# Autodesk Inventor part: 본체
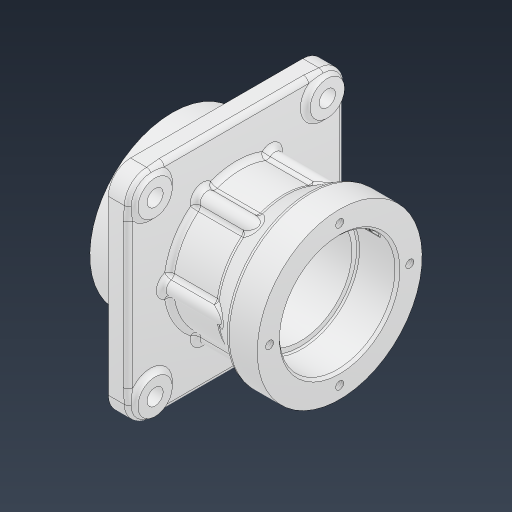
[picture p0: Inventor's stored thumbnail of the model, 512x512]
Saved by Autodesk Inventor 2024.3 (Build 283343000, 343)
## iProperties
Created: 2025-08
Part Number: 본체
Material: 알루미늄 6061
Document SubType Name: Modeling
Designer: user
Density: 2.7 g/cm^3
Appearance: 알루미늄 - 평지
Mass: 392.632 g
Surface Area: 389.994 cm^2
Volume: 145.419 cm^3
Author: user
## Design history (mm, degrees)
sketch "스케치1"
  geometry: L1 (34, 33.5)-(34, 0); L2 (34, 0)-(-34, 0); L3 (-34, 0)-(-34, 33.5); L4 (-34, 33.5)-(34, 0); L5 (34, 33.5)-(-34, 0); L6 (-21, 38.5)-(-16, 38.5); L7 (-16, 38.5)-(-16, 0); L8 (-16, 0)-(-21, 0); L9 (-21, 0)-(-21, 38.5); L10 (-21, 38.5)-(-16, 0); L11 (-16, 38.5)-(-21, 0); L12 (22, 33.5)-(22, 0); L13 (12, 27.5)-(12, 0); L14 (21.821, 27.5)-(12, 27.5); L15 (-34, 33.5)-(-20.351, 33.5); L16 (22, 33.5)-(34, 33.5); L17 (22, 33.5)-(12, 27.5); L18 (12, 27.5)-(-16, 27.5); L19 (-20.351, 33.5)-(-16, 33.5); 10 further points
  constraints: 38 end point, 8 midpoint, 7 perpendicular, 7 point on line, 6 parallel, 4 horizontal, 1 coincident, 1 vertical
  dimensions: "d0" = 68 distance of L1.end L2.end; "d3" = 5 distance of L7.end L8.end; "d5" = 13 distance from line of point (-34, 16.75) L9; "d6" = 77 diameter of L6 L2; "d14" = 12 distance from line of point (34, 16.75) L12; "d16" = 22 distance between parallel lines of L1 L13; "d17" = 55 diameter of L14 L2; "d18" = 67 diameter of L16 L2
revolve "회전1" sketch "스케치1" stored, may be unused: angle "d7" = 360 deg
sketch "스케치4"
  geometry: L1 (44, -44)-(-44, -44); L2 (-44, -44)-(-44, 44); L3 (-44, 44)-(44, 44); L4 (44, 44)-(44, -44); L5 (44, -44)-(-44, 44); L6 (-44, -44)-(44, 44); C1 r 27.5 at (0, 0) reference
  constraints: 12 end point, 2 midpoint, 2 parallel, 1 horizontal, 1 perpendicular
  dimensions: "d19" = 88 distance of L2.end L3.end; "d20" = 88 distance of L1.end L2.end
extrude "돌출2" join sketch "스케치4" distance "d21" = 8; taper "d22" = 0 deg
fillet "모깎기2" dims "d23" = 9
fillet "모깎기3" dims "d24" = 2
fillet "모깎기4" dims "d25" = 2
fillet "모깎기5" dims "d26" = 2
fillet "모깎기6" dims "d27" = 2
sketch "스케치5"
  geometry: C1 r 7 at (-35, 35); C2 r 7 at (35, 35); C3 r 7 at (35, -35); C4 r 7 at (-35, -35); A1 r 9 centre (-35, -35) between (-44, -35) and (-35, -44) reference; A2 r 9 centre (35, -35) between (35, -44) and (44, -35) reference; A3 r 9 centre (35, 35) between (44, 35) and (35, 44) reference; A4 r 9 centre (-35, 35) between (-35, 44) and (-44, 35) reference
  constraints: 4 centre point, 4 coincident
  dimensions: "d28" = 14 diameter of C1; "d29" = 14 diameter of C2; "d30" = 14 diameter of C3; "d31" = 14 diameter of C4
extrude "돌출3" join sketch "스케치5" distance "d32" = 2; taper "d33" = 0 deg
fillet "모깎기7" dims "d34" = 2
sketch "스케치6"
  geometry: C1 r 7 at (-70, 0) reference; C2 r 7 at (-70, -70) reference; C3 r 7 at (0, 0) reference; C4 r 7 at (0, -70) reference; C5 r 27.5 at (-35, -35) reference; C6 r 3.3 at (0, 0); C7 r 3.3 at (0, -70); C8 r 3.3 at (-70, -70); C9 r 3.3 at (-70, 0); 1 further point
  constraints: 4 centre point, 4 coincident
  dimensions: "d35" = 6.6 diameter of C6; "d36" = 6.6 diameter of C7; "d37" = 6.6 diameter of C8; "d38" = 6.6 diameter of C9
extrude "돌출4" cut sketch "스케치6" extent not by distance; stored distance "d39" = 0; taper "d40" = 0 deg
fillet "모깎기8" dims "d41" = 2
fillet "모깎기9" dims "d42" = 2
sketch "스케치7"
  geometry: L1 (-21, -36.5)-(-21, -35.5) reference; L2 (-23, -33.5)-(-34, -33.5) reference; L3 (-34, -33.5)-(-34, 33.5) reference; L4 (-34, 33.5)-(-23, 33.5) reference; L5 (-21, 35.5)-(-21, 36.5) reference; L6 (-19, 38.5)-(-16, 38.5) reference; L7 (-16, 38.5)-(-16, 44) reference; L8 (-16, 44)-(-10, 44) reference; L9 (-8, 42)-(-8, 29.5) reference; L10 (-6, 27.5)-(11.446, 27.5) reference; L11 (12.475, 27.785)-(21.525, 33.215) reference; L12 (22.554, 33.5)-(34, 33.5) reference; L13 (34, 33.5)-(34, -33.5) reference; L14 (34, -33.5)-(22.554, -33.5) reference; L15 (21.525, -33.215)-(12.475, -27.785) reference; L16 (11.446, -27.5)-(-6, -27.5) reference; L17 (-8, -29.5)-(-8, -42) reference; L18 (-10, -44)-(-16, -44) reference; L19 (-16, -44)-(-16, -38.5) reference; L20 (-16, -38.5)-(-19, -38.5) reference; L21 (34, 0)-(-34, 0); L22 (18, 23.5)-(18, 0); L23 (18, 23.5)-(34, 23.5); L24 (-18, 23.5)-(-18, 0); L25 (-18, 23.5)-(-34, 23.5); L26 (-34, 33.5)-(-34, -33.5) reference; L27 (-34, 0.1)-(-34, 23.5); L28 (34, 23.5)-(34, 0); L29 (18, 21)-(-18, 21); A1 r 2 centre (-19, -36.5) between (-21, -36.5) and (-19, -38.5) reference; A2 r 2 centre (-23, -35.5) between (-21, -35.5) and (-23, -33.5) reference; A3 r 2 centre (-23, 35.5) between (-23, 33.5) and (-21, 35.5) reference; A4 r 2 centre (-19, 36.5) between (-19, 38.5) and (-21, 36.5) reference; A5 r 2 centre (-10, 42) between (-8, 42) and (-10, 44) reference; A6 r 2 centre (-6, 29.5) between (-8, 29.5) and (-6, 27.5) reference; A7 r 2 centre (11.446, 29.5) between (11.446, 27.5) and (12.475, 27.785) reference; A8 r 2 centre (22.554, 31.5) between (22.554, 33.5) and (21.525, 33.215) reference; A9 r 2 centre (22.554, -31.5) between (21.525, -33.215) and (22.554, -33.5) reference; A10 r 2 centre (11.446, -29.5) between (12.475, -27.785) and (11.446, -27.5) reference; A11 r 2 centre (-6, -29.5) between (-6, -27.5) and (-8, -29.5) reference; A12 r 2 centre (-10, -42) between (-10, -44) and (-8, -42) reference; 3 further points
  constraints: 16 end point, 7 point on line, 5 perpendicular, 2 collinear, 2 midpoint, 1 coincident, 1 horizontal
  dimensions: "d43" = 16 distance between parallel lines of L13 L22; "d44" = 47 diameter of L22.start L21; "d45" = 16 distance between parallel lines of L3 L24; "d46" = 47 diameter of L24.start L21; "d47" = 42 diameter of L29 L21
revolve "회전2" sketch "스케치7" stored, may be unused: angle "d48" = 90 deg
chamfer "모따기1" distance "d49" = 1; stored, may be unused: second distance "d50" = 2, angle "d51" = 45 deg
fillet "모깎기10" dims "d52" = 0.6
sketch "스케치8"
  geometry: L1 (33.5, 0)-(-33.5, 0); L2 (0, 28.5)-(0, 0); C1 r 24.5 at (0, 0) reference; C2 r 29.5 at (0, 0) reference; C3 r 2 at (-28.5, 0); C4 r 2 at (28.5, 0); C5 r 2 at (0, 28.5); C6 r 2 at (0, -28.5); A1 r 33.5 centre (0, 0) between (33.5, 0) and (-33.5, 0) reference; A2 r 28.5 centre (0, 0) between (-28.5, 0) and (28.5, 0); A3 r 33.5 centre (0, 0) between (33.5, 0) and (-33.5, 0) reference
  constraints: 5 centre point, 5 point on circle, 4 end point, 2 point on line, 1 coincident, 1 horizontal, 1 perpendicular, 1 symmetric about line, 1 other
  dimensions: "d54" = 57 diameter of A2; "d56" = 67 distance of L1.start L1.end; "d57" = 4 diameter of C3; "d58" = 4 diameter of C4; "d59" = 4 diameter of C5
hole "구멍1" sketch "스케치8" at (0, 28.5), (28.5, 0), (0, -28.5), (-28.5, 0) diameter "d60" = 3.242; stored, may be unused: countersink angle "d64" = 90 deg, drill point angle "d66" = 118 deg; dims "d61" = 8, "d62" = 10, "d63" = 6, "d65" = 10
sketch "스케치9"
  geometry: L1 (0, 33.5)-(0, -33.5); L2 (33.5, 0)-(-33.5, 0); C1 r 24.5 at (0, 0) reference; C2 r 2 at (0, 28.5); C3 r 2 at (28.5, 0); C4 r 2 at (0, -28.5); C5 r 2 at (-28.5, 0); A1 r 33.5 centre (0, 0) between (0, 33.5) and (0, -33.5) reference; A2 r 28.5 centre (0, 0) between (0, 28.5) and (28.5, 0); A3 r 33.5 centre (0, 0) between (0, 33.5) and (0, -33.5) reference
  constraints: 8 point on circle, 5 centre point, 4 end point, 4 point on line, 1 coincident, 1 horizontal, 1 vertical
  dimensions: "d67" = 57 diameter of A2; "d68" = 67 distance of L2.start L2.end; "d69" = 67 distance of L1.start L1.end; "d70" = 4 diameter of C2; "d71" = 4 diameter of C3; "d72" = 4 diameter of C4; "d73" = 4 diameter of C5
hole "구멍2" sketch "스케치9" at (-28.5, 0), (0, -28.5), (28.5, 0), (0, 28.5) diameter "d74" = 3.242; stored, may be unused: countersink angle "d78" = 90 deg, drill point angle "d80" = 118 deg; dims "d75" = 8, "d76" = 4, "d77" = 2, "d79" = 10
sketch "스케치10"
  geometry: L1 (0, 0)-(0, -27.5); C1 r 21 at (0, 0) reference; C2 r 3 at (0, -27.5); C3 r 3 at (23.816, -13.75); C4 r 3 at (23.816, 13.75); C5 r 3 at (0, 27.5); C6 r 3 at (-23.816, 13.75); C7 r 3 at (-23.816, -13.75); 1 further point
  constraints: 6 centre point, 2 end point, 1 coincident, 1 vertical, 1 vertical alignment, 14 other
  dimensions: "d81" = 6 diameter of C2; "d85" = 360 deg dimension on L1.start C2.centre (derived)
extrude "돌출5" join sketch "스케치10" extent not by distance; stored distance "d87" = 0; taper "d88" = 0 deg
fillet "모깎기11" dims "d89" = 2
sketch "스케치11" dims "d0" = 68, "d3" = 5, "d5" = 13, "d6" = 77, "d14" = 12, "d16" = 22, "d17" = 55, "d18" = 67
  geometry: L1 (-34, -33.5)-(-34, 33.5) reference; 2 further points
  constraints: 1 horizontal alignment, 1 other
  dimensions: "d90" = 6 distance from line of L1 point (-28, 0)
feature "엠보싱1" sketch "스케치11" dims "d0" = 68, "d3" = 5, "d5" = 13, "d6" = 77, "d14" = 12, "d16" = 22, "d17" = 55, "d18" = 67, "d91" = 0.5, "d92" = 0
node "솔리드1"
node "절단 모서리 투영2"
node "절단 모서리 투영3"
node "절단 모서리 투영4"
feature "A9D066F2-1C7D-4E18-AEED-F7BC21143FA4" dims "d60" = 3.242, "d61" = 8, "d62" = 10, "d63" = 6, "d64" = 90 deg, "d65" = 10, "d66" = 118 deg
other parameters: "d2" = 67
